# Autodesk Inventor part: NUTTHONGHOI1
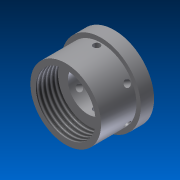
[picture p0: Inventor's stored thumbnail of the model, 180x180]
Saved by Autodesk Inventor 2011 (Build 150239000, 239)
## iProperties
Created: 2011-04
Part Number: NUTTHONGHOI1
Document SubType Name: Modeling
Designer: TRINH
Density: 1 g/cm^3
Author: TRINH
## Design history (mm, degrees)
sketch "Sketch1"
  geometry: L1 (0, 0)-(0, -43.486); L2 (18, -1.523)-(18, -7.523); L3 (0, -1.523)-(18, -1.523); L4 (18, -7.523)-(16, -7.523); L5 (16, -7.523)-(16, -23.523); L6 (16, -23.523)-(13.5, -23.523); L7 (13.5, -23.523)-(13.5, -13.523); L8 (13.5, -13.523)-(9, -13.523); L9 (9, -13.523)-(9, -5.523); L10 (9, -5.523)-(0, -5.523); 1 further point
  constraints: 20 end point, 7 perpendicular, 2 parallel, 2 point on line, 1 vertical
  dimensions: "d0" = 6 distance of L2.start L2.end; "d1" = 18 distance between parallel lines of L1 L2; "d2" = 2 distance of L2.end L4.end; "d3" = 16 distance of L4.end L5.end; "d4" = 2.5 distance of L5.end L6.end; "d5" = 10 distance of L6.end L7.end; "d6" = 9 distance from line of L1 L8.end; "d7" = 4 distance from line of L9.end L3; "d19" = 0 horizontal distance of point (0, 0) L3.start; "d21" = 0 distance of L1.start point (0, 0); "d22" = 43.48624 distance of L1.start L1.end; "d23" = 1.52294 distance from line of L1.start L3
revolve "Revolution1" sketch "Sketch1" stored, may be unused: angle "d8" = 90 deg
workplane "Work Plane1"
  workaxis "Work Axis1"
sketch "Sketch2"
  geometry: L1 (-3, -18)-(-3, 18) reference; C1 r 1.5 at (5, 0); 1 further point
  constraints: 1 centre point
  dimensions: "d10" = 8 distance from line of C1.centre L1; "d11" = 3 diameter of C1
extrude "Extrusion1" cut sketch "Sketch2" stored distance "d12" = 10; taper "d13" = 0 deg
pattern_circular "Circular Pattern1" dims angle "d15" = 360 deg
thread "Thread1" dims "d17" = 10, "d18" = 0
body "Solid1"
other parameters: "d9" = 90 deg
